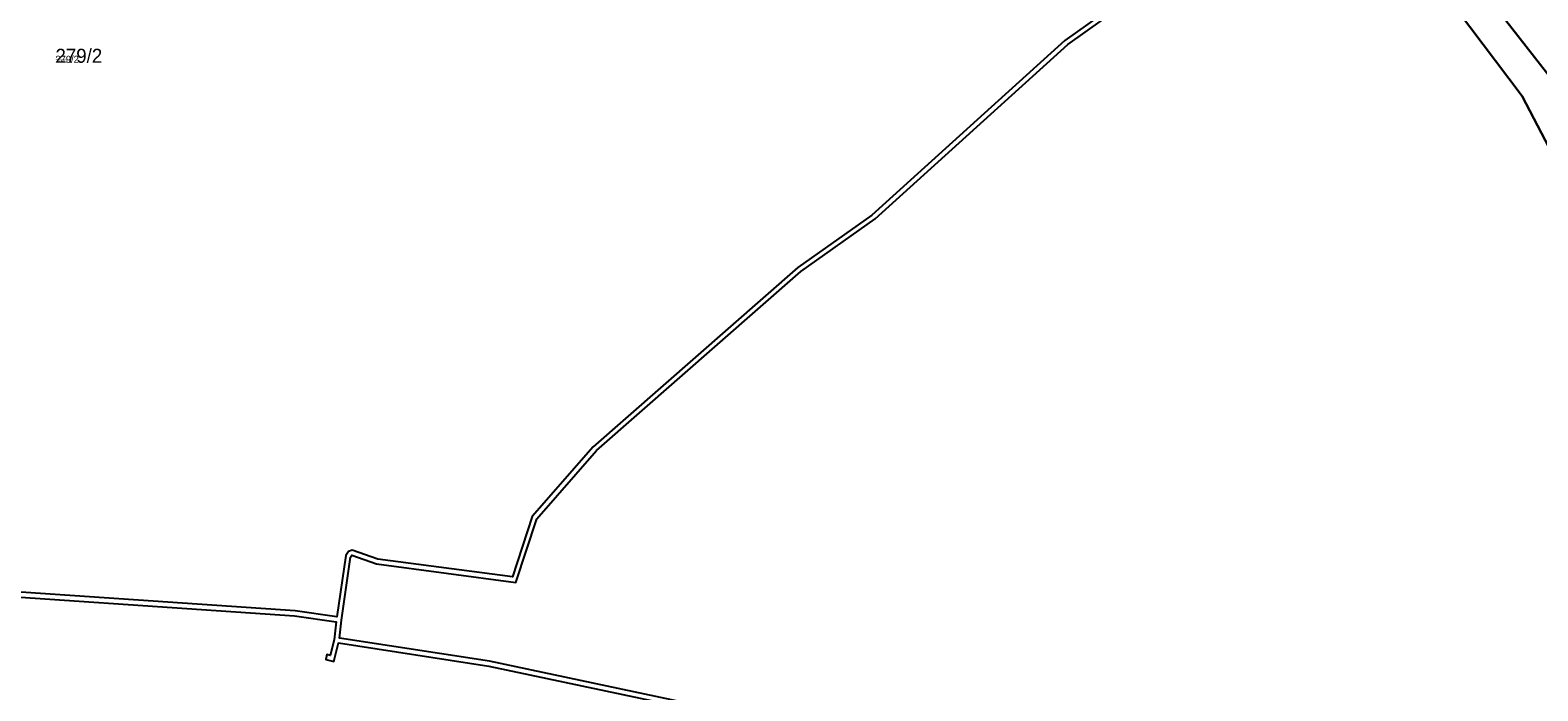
# Model space of a CAD drawing. Extents: x -759873 to -758487, y -975024 to -973516.
# Drawn here: x -759000.3 to -758816.8, y -974535.9 to -974455.6 of the extents above; entities that cross this region are included whole.
import ezdxf

# ---------------------------------------------------------------- set-up
doc = ezdxf.new("R2010")
doc.units = 0
for name, color, linetype in [('KAT_02_hranice parcel', 7, 'Continuous'), ('KAT_03_1000_čísla parcelní', 7, 'Continuous'), ('KAT_03_250_čísla parcelní', 7, 'Continuous'), ('KAT_03_500_čísla parcelní', 7, 'Continuous'), ('KAT_10_věcná břemena', 7, 'Continuous'), ('KAT_14_plocha_pozemek', 7, 'Continuous')]:
    doc.layers.add(name, color=color, linetype=linetype)

msp = doc.modelspace()

# ---------------------------------------------------------------- linework, layer by layer
at = {"layer": 'KAT_02_hranice parcel'}
for points in [[(-758697.83, -974596.44), (-758723.53, -974581.66), (-758758.5, -974544.23), (-758796.32, -974507.97), (-758808.82, -974475.92), (-758814.76, -974462.01), (-758845.88, -974422.17), (-758854.49, -974404.19), (-758863.43, -974395.34), (-758883.13, -974381.25), (-758920.39, -974363.49)], [(-758867.55, -974396.24), (-758858.57, -974407.31), (-758849.06, -974423.37), (-758818.74, -974463.59), (-758812.66, -974475.2), (-758797.73, -974511.01), (-758760.58, -974546.71), (-758726.38, -974585.65), (-758699.89, -974599.55)]]:
    msp.add_lwpolyline(points, dxfattribs=at)
at = {"layer": 'KAT_10_věcná břemena'}
for points in [[(-758841.5, -974433.4), (-758874.38, -974456.82), (-758897.84, -974478.04), (-758906.86, -974484.41), (-758931.78, -974506.24), (-758939.17, -974514.7), (-758941.59, -974522.06), (-758957.97, -974519.89), (-758961.1, -974518.79), (-758961.54, -974518.97), (-758961.85, -974519.44), (-758962.94, -974526.92), (-758968.02, -974526.18), (-759014.55, -974523.01)], [(-758918.97, -974537.69), (-758944.37, -974532.32), (-758962.64, -974529.49), (-758962.39, -974527.3), (-758961.27, -974519.66), (-758961.12, -974519.42), (-758958.11, -974520.47), (-758941.17, -974522.72), (-758938.63, -974515), (-758931.36, -974506.66), (-758906.48, -974484.89), (-758897.46, -974478.5), (-758874, -974457.28), (-758841.14, -974433.88)], [(-759014.59, -974523.61), (-758968.08, -974526.78), (-758963.02, -974527.52), (-758963.27, -974529.69), (-758963.75, -974531.61), (-758964.16, -974531.51), (-758964.3, -974532.09), (-758963.31, -974532.33), (-758962.75, -974530.08), (-758944.47, -974532.92), (-758918.95, -974538.31)]]:
    msp.add_lwpolyline(points, dxfattribs=at)
at = {"layer": 'KAT_14_plocha_pozemek'}
for points in [[(-758760.58, -974546.71), (-758797.73, -974511.01), (-758812.66, -974475.2), (-758818.74, -974463.59), (-758849.06, -974423.37), (-758858.57, -974407.31), (-758867.55, -974396.24), (-758911.81, -974379.4), (-758952.35, -974369.35), (-758971.41, -974365.53), (-758992.93, -974364.06), (-759006.26, -974363.99)], [(-758783.72, -974438.99), (-758822.73, -974398.57), (-758833.47, -974388.69), (-758847.81, -974380.27), (-758862.06, -974374.57), (-758886.55, -974368.01), (-758901.31, -974364.72), (-758920.39, -974363.49), (-758883.13, -974381.25), (-758863.43, -974395.34), (-758854.49, -974404.19), (-758845.88, -974422.17), (-758814.76, -974462.01)]]:
    msp.add_lwpolyline(points, dxfattribs=at)
msp.add_lwpolyline([(-758697.83, -974596.44), (-758723.53, -974581.66), (-758758.5, -974544.23), (-758796.32, -974507.97), (-758808.82, -974475.92), (-758814.76, -974462.01), (-758845.88, -974422.17), (-758854.49, -974404.19), (-758863.43, -974395.34), (-758883.13, -974381.25), (-758920.39, -974363.49), (-758930.04, -974363.17), (-758881.44, -974386.63), (-758867.55, -974396.24), (-758858.57, -974407.31), (-758849.06, -974423.37), (-758818.74, -974463.59), (-758812.66, -974475.2), (-758797.73, -974511.01), (-758760.58, -974546.71), (-758726.38, -974585.65), (-758699.89, -974599.55)], close=True, dxfattribs=at)

# ---------------------------------------------------------------- texts
at = {"layer": 'KAT_03_1000_čísla parcelní'}
msp.add_text('279/2', height=1.7, dxfattribs=at).set_placement((-758997.18, -974459.52))
at = {"layer": 'KAT_03_250_čísla parcelní'}
msp.add_text('279/2', height=0.425, dxfattribs=at).set_placement((-758997.18, -974459.52))
at = {"layer": 'KAT_03_500_čísla parcelní'}
msp.add_text('279/2', height=0.85, dxfattribs=at).set_placement((-758997.18, -974459.52))

doc.saveas('drawing.dxf')
